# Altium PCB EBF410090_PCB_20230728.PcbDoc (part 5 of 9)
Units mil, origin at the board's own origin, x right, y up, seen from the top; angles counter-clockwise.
Board outline 5393.69 x 3858.26 mil, 6 copper layers (TOP, GND02, ART03, ART04, PWR05, BOTTOM), stack 47.2 mil thick; 570 components, 437 nets, 2015 pads, 1260 vias.
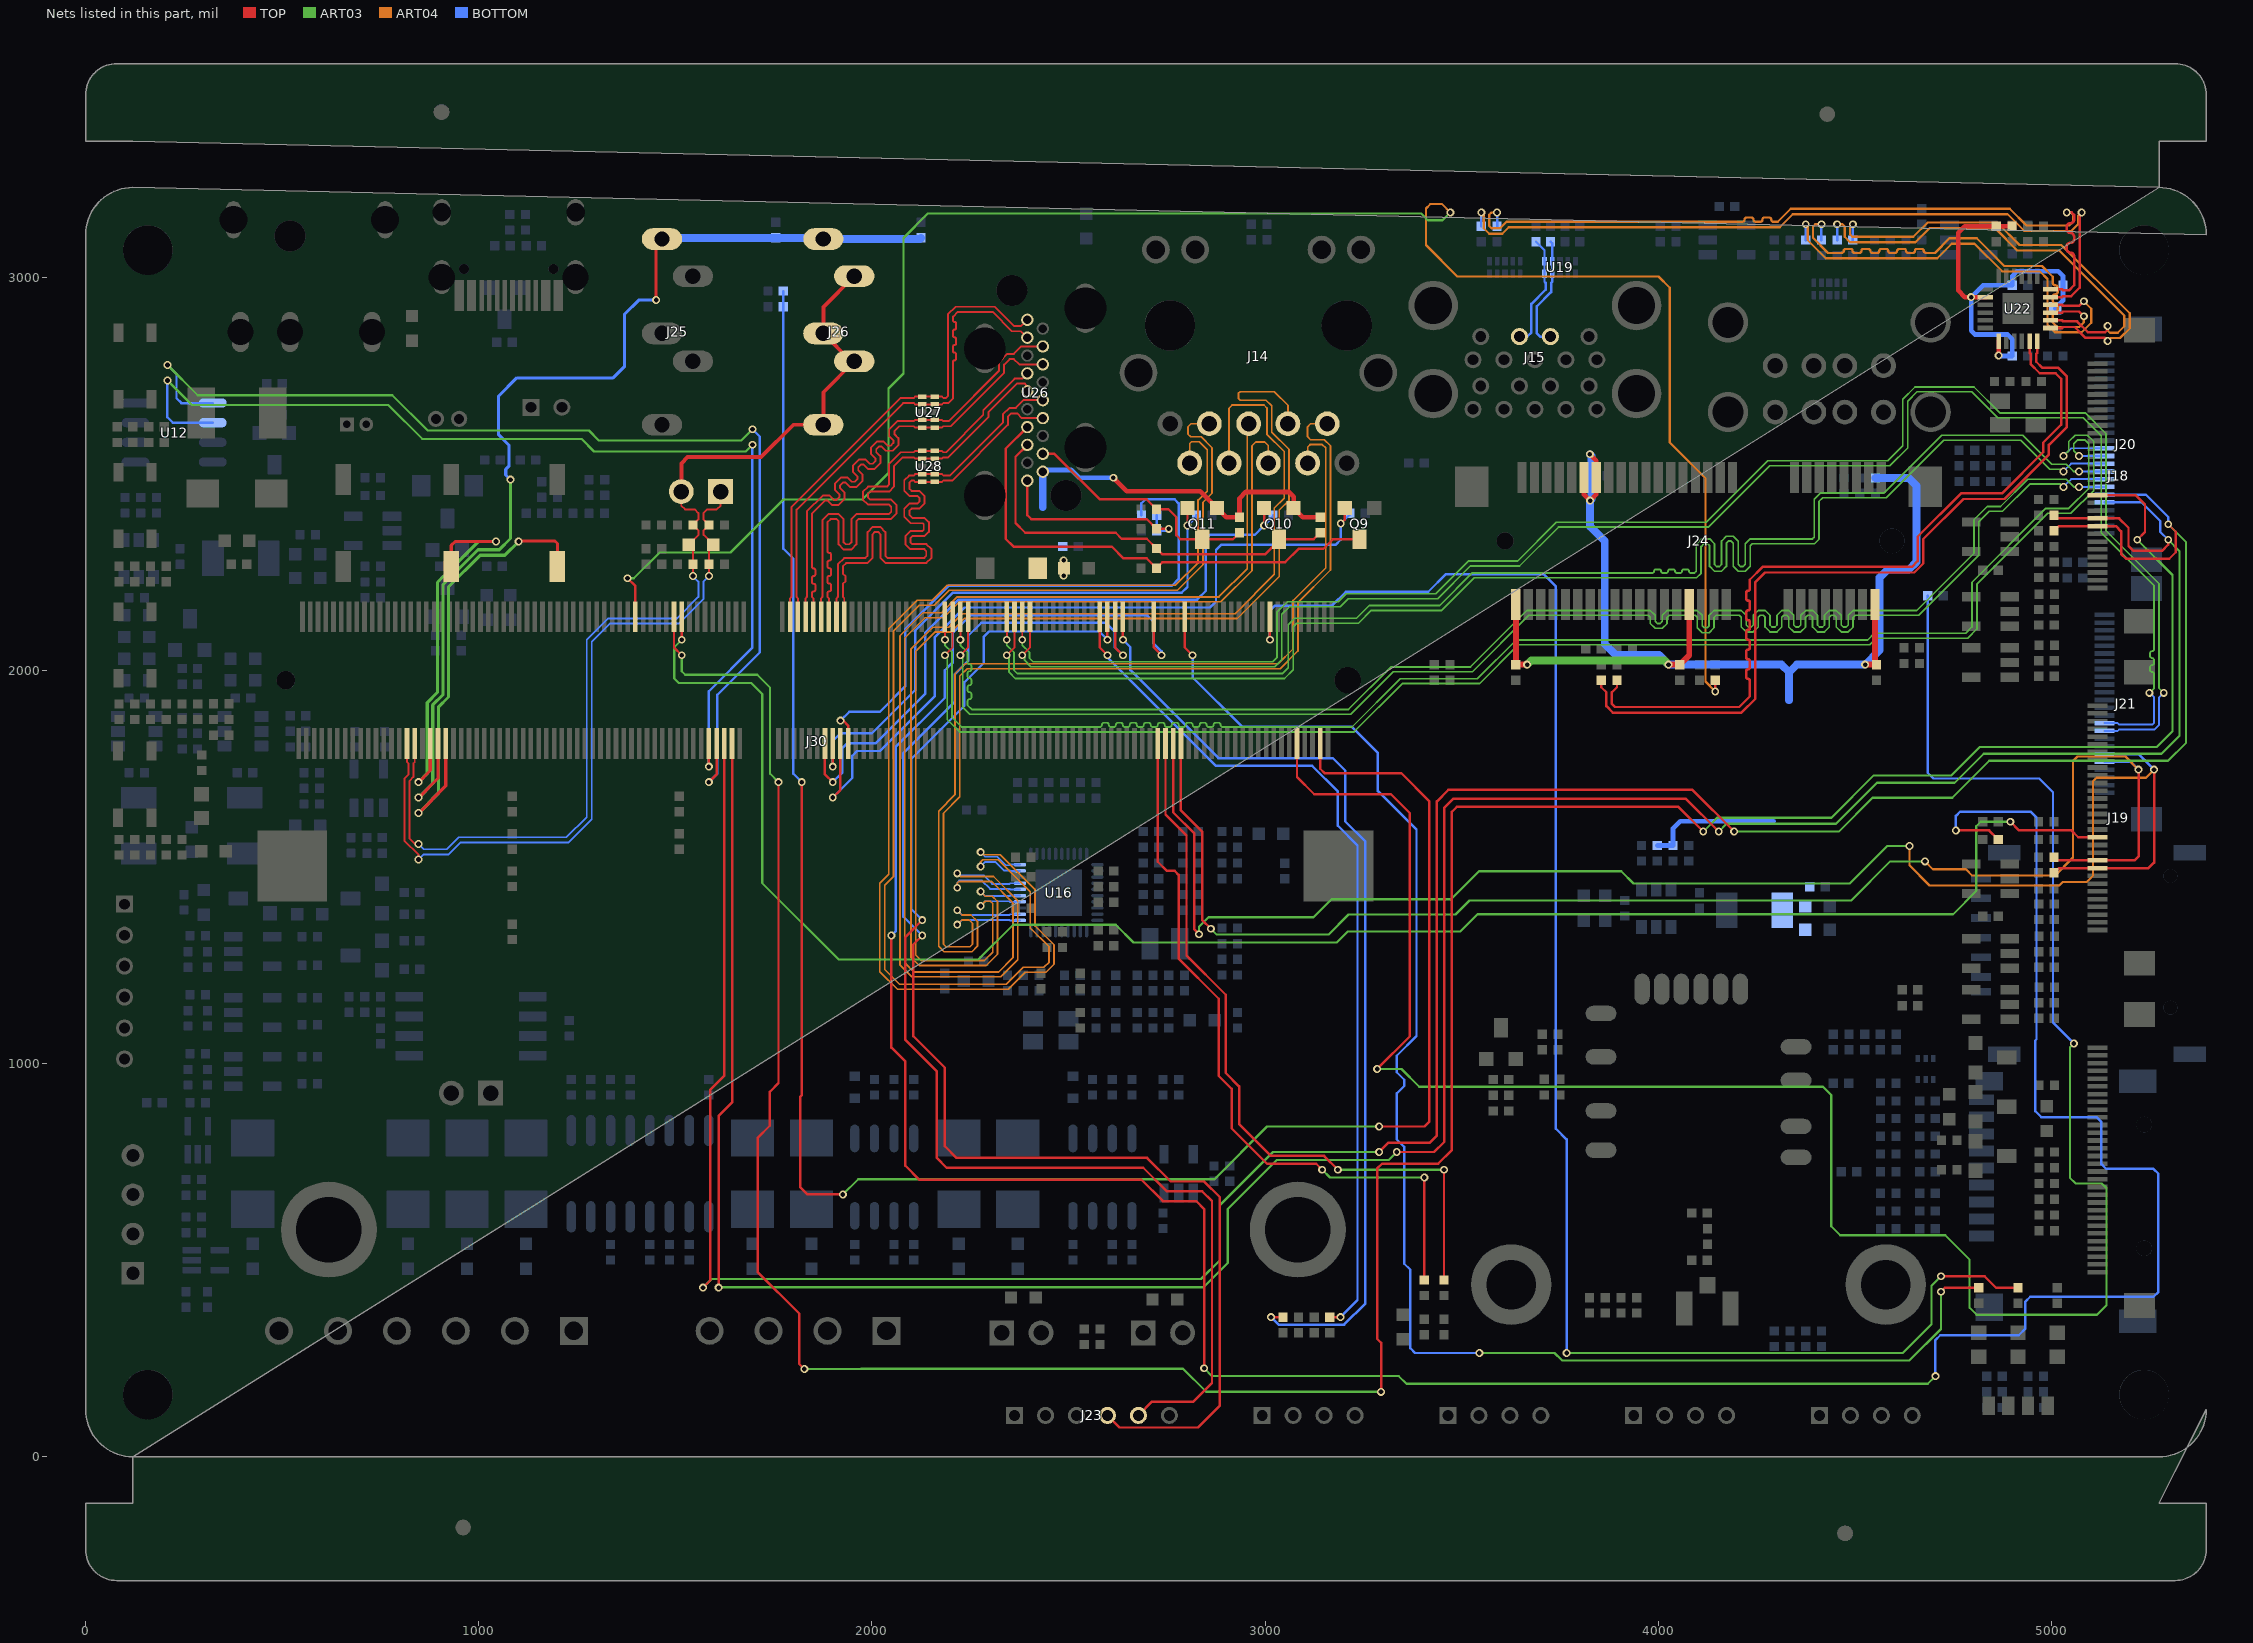
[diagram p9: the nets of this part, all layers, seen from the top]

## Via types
v1: diameter 20, hole 12, TOP to BOTTOM, 1260 vias

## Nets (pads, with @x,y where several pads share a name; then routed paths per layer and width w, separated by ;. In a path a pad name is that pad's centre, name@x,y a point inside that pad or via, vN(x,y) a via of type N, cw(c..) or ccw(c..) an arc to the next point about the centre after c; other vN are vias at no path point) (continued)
GPIO2_B7: J30.17 R48.2 | length 4171.4
  TOP w6.16: v1(3012.26,2078.07) J30.17@3012.28,2136.54 ; v1(4719,459.05) 4829.95,459.05 4859.32,429.68 R48.2@4915,429.68
  ART03 w5.61: v1(3766.91,263.81) 4622.18,263.81 4695,336.63 4695,435.05 v1(4719,459.05)
  BOTTOM w6.16: v1(3012.26,2078.07) 3012.26,2152.26 3025,2165 3170,2165 3205,2200 3415,2200 3460,2245 3708.42,2245 3739.66,2213.76 3739.66,834.34 3766.91,807.09 v1(3766.91,263.81)
GPIO2_C0: J30.39 R49.2 | length 3909.3
  TOP w6.16: J30.39@2795.74,2136.54 2795.74,2058.37 v1(2815.41,2038.7) ; v1(4719,419.68) 4729,429.68 R49.2@4815,429.68
  ART03 w5.61: v1(3545,263.81) 3736.2,263.81 3755.01,245 4639,245 4719,325 v1(4719,419.68)
  BOTTOM w6.16: v1(2815.41,2038.7) 2815.41,1982.59 2941,1857 3220,1857 3287,1790 3287,1693 3385,1595 3385,1070 3335,1020 3335,977.99 3354.08,958.91 3354.08,943.09 3335,924.01 3335,806.99 3354.08,787.91 3354.08,490.91 3369.08,475.91 3369.08,276.13 3381.4,263.81 v1(3545,263.81)
HDMI_5V: C131.1 D27.1 D32.2 Q10.1 Q11.1 R158.1 R160.1 U26.18 | length 945.4
  TOP w12: v1(2613.99,2490) 2647.99,2456 2835,2456 Q11.1@2877.5,2413.5 2901.32,2389.68 R160.1@2935,2389.68 2935,2438 2951,2454 3060.5,2454 3072.5,2442 Q10.1@3072.5,2413.5 3096.32,2389.68 R158.1@3140,2389.68
  BOTTOM w12: U26.18@2434.54,2505.36 2439.18,2510 2507,2510 2527,2490 v1(2613.99,2490)
  BOTTOM w20: 2434.54,2415.46 U26.18@2434.54,2505.36
  other v1: 2487.48,2240.63 2487.48,2280
HDMI_TX0N_PORT: J30.131 U26.9 U28.4 U28.7 | length 1279.5
  TOP w4.88: J30.131@1890.23,2136.54 1890.23,2183.41 1886.83,2186.81 1886.83,2196.69 cw(c1891.47,2196.69) 1891.47,2201.33 ; 1891.47,2220.85 cw(c1891.47,2225.49) 1886.83,2225.49 1886.83,2235.73 cw(c1891.47,2235.73) 1891.47,2240.37 ; 1891.47,2259.89 cw(c1891.47,2264.53) 1886.83,2264.53 1886.83,2274.77 cw(c1891.47,2274.77) 1891.47,2279.41 ; 1891.47,2298.93 cw(c1891.47,2303.57) 1886.83,2303.57 1886.83,2376.83 1894.61,2384.61 1910.23,2384.61 1915.11,2379.73 1915.11,2320.42 1927.53,2308 1947.97,2308 1960.39,2320.42 1960.39,2379.73 1965.27,2384.61 2047.84,2384.61 2062,2398.77 2062,2421 2047.84,2435.16 1994.76,2435.16 1989.88,2440.04 1989.88,2448.8 1995.76,2454.68 2043.58,2454.68 2056,2467.1 2056,2519.21 2078.88,2542.09 2106.53,2542.09 2109.93,2538.69 U28.7@2128.25,2538.69 U28.4@2159.75,2538.69 2178.08,2538.69 2181.48,2542.09 2193.73,2542.09 2296,2644.36 2296,2657 2368.27,2729.27 2388.73,2729.27 2395.17,2722.83 U26.9@2395.17,2709.97 ; 1891.48,2201.33 ccw(c1891.48,2205.97) 1896.12,2205.97 1896.12,2216.21 ccw(c1891.48,2216.21) 1891.48,2220.85 ; 1891.48,2240.37 ccw(c1891.48,2245.01) 1896.12,2245.01 1896.12,2255.25 ccw(c1891.48,2255.25) 1891.48,2259.89 ; 1891.48,2279.41 ccw(c1891.48,2284.05) 1896.12,2284.05 1896.12,2294.29 ccw(c1891.48,2294.29) 1891.48,2298.93
HDMI_TX0P_PORT: J30.133 U26.7 U28.5 U28.6 | length 1259
  TOP w4.88: J30.133@1870.55,2136.54 1870.55,2183.41 1873.95,2186.81 1873.95,2382.17 1889.27,2397.49 1915.57,2397.49 1927.99,2385.07 1927.99,2325.76 1932.87,2320.88 1942.63,2320.88 1947.51,2325.76 1947.51,2385.07 1959.93,2397.49 2042.5,2397.49 2049.12,2404.11 2049.12,2415.66 2042.5,2422.28 1989.42,2422.28 1977,2434.7 1977,2454.14 1990.42,2467.56 2038.24,2467.56 2043.12,2472.44 2043.12,2524.55 2073.54,2554.97 2106.53,2554.97 2109.93,2558.37 U28.6@2128.25,2558.37 U28.5@2159.75,2558.37 2178.08,2558.37 2181.48,2554.97 2188.39,2554.97 2283.12,2649.7 2283.12,2662.34 2362.93,2742.15 2381.88,2742.15 U26.7@2395.17,2755.44
HDMI_TX1N_PORT: J30.135 U26.6 U27.1 U27.10 | length 1231.2
  TOP w4.88: J30.135@1850.86,2136.54 1850.86,2183.41 1847.46,2186.81 1847.46,2196.69 cw(c1851.73,2196.69) 1851.73,2200.96 ccw(c1851.73,2205.23) 1856,2205.23 1856,2216.21 ccw(c1851.73,2216.21) 1851.73,2220.48 cw(c1851.73,2224.75) 1847.46,2224.75 1847.46,2235.73 cw(c1851.73,2235.73) 1851.73,2240 ccw(c1851.73,2244.27) 1856,2244.27 1856,2255.25 ccw(c1851.73,2255.25) 1851.73,2259.52 cw(c1851.73,2263.79) 1847.46,2263.79 1847.46,2398.91 1880.22,2431.67 1887.12,2431.67 1897.72,2421.07 1915.28,2421.07 1929.78,2435.57 1929.78,2453.13 1919.18,2463.73 1919.18,2470.63 1926.09,2477.54 1932.99,2477.54 1943.59,2466.94 1961.15,2466.94 1975.65,2481.44 1975.65,2499 1965.05,2509.6 1965.05,2516.5 1971.96,2523.41 1978.86,2523.41 1989.46,2512.81 2007.02,2512.81 2021.52,2527.31 2021.52,2544.87 2010.92,2555.47 2010.92,2562.37 2017.83,2569.28 2024.73,2569.28 2035.33,2558.68 2052.89,2558.68 2067.39,2573.18 2067.39,2590.74 2056.79,2601.34 2056.79,2608.24 2069.58,2621.03 2106.53,2621.03 2109.93,2617.63 U27.10@2128.25,2617.63 U27.1@2159.75,2617.63 2178.08,2617.63 2181.48,2621.03 2200.03,2621.03 2336,2757 2336,2778 2350,2792 2361,2792 2374.57,2778.43 U26.6@2434.54,2778.43
HDMI_TX1P_PORT: J30.137 U26.4 U27.2 U27.9 | length 1235.3
  TOP w4.88: J30.137@1831.18,2136.54 1831.18,2183.41 1834.58,2186.81 1834.58,2404.25 1874.88,2444.55 1892.46,2444.55 1903.06,2433.95 1909.94,2433.95 1916.9,2440.91 1916.9,2447.79 1906.3,2458.39 1906.3,2475.97 1920.75,2490.42 1938.33,2490.42 1948.93,2479.82 1955.81,2479.82 1962.77,2486.78 1962.77,2493.66 1952.17,2504.26 1952.17,2521.84 1966.62,2536.29 1984.2,2536.29 1994.8,2525.69 2001.68,2525.69 2008.64,2532.65 2008.64,2539.53 1998.04,2550.13 1998.04,2567.71 2012.49,2582.16 2030.07,2582.16 2040.67,2571.56 2047.55,2571.56 2054.51,2578.52 2054.51,2585.4 2043.91,2596 2043.91,2613.58 2064.24,2633.91 2106.53,2633.91 2109.93,2637.31 U27.9@2128.25,2637.31 U27.2@2159.75,2637.31 2178.08,2637.31 2181.48,2633.91 2194.69,2633.91 2323.12,2762.34 2323.12,2783.34 2344.66,2804.88 2361,2804.88 2380.06,2823.94 U26.4@2434.54,2823.94
HDMI_TX2N_PORT: J30.139 U26.3 U27.4 U27.7 | length 1248
  TOP w4.88: J30.139@1811.49,2136.54 1811.49,2183.41 1808.09,2186.81 1808.09,2409.09 2079.09,2680.09 2106.53,2680.09 2109.93,2676.69 U27.7@2128.25,2676.69 U27.4@2159.75,2676.69 2178.08,2676.69 2181.48,2680.09 2193.73,2680.09 2206.15,2692.51 2206.15,2784.83 cw(c2210.07,2784.83) 2210.07,2788.75 ; 2210.07,2808.27 cw(c2210.07,2812.19) 2206.15,2812.19 2206.15,2823.87 cw(c2210.07,2823.87) 2210.07,2827.79 ; 2210.07,2847.31 cw(c2210.07,2851.23) 2206.15,2851.23 2206.15,2862.91 cw(c2210.07,2862.91) 2210.07,2866.83 ; 2210.07,2886.35 cw(c2210.07,2890.27) 2206.15,2890.27 2206.15,2900.15 2218.12,2912.12 2306.66,2912.12 2356.11,2862.67 2378.88,2862.67 U26.3@2395.17,2846.38 ; 2210.08,2788.75 ccw(c2210.08,2792.67) 2214,2792.67 2214,2804.35 ccw(c2210.08,2804.35) 2210.08,2808.27 ; 2210.08,2827.79 ccw(c2210.08,2831.71) 2214,2831.71 2214,2843.39 ccw(c2210.08,2843.39) 2210.08,2847.31 ; 2210.08,2866.83 ccw(c2210.08,2870.75) 2214,2870.75 2214,2882.43 ccw(c2210.08,2882.43) 2210.08,2886.35
HDMI_TX2P_PORT: J30.141 U26.1 U27.5 U27.6 | length 1242.4
  TOP w4.88: J30.141@1791.81,2136.54 1791.81,2183.41 1795.21,2186.81 1795.21,2414.43 2073.75,2692.97 2106.53,2692.97 2109.93,2696.37 U27.6@2128.25,2696.37 U27.5@2159.75,2696.37 2178.08,2696.37 2181.48,2692.97 2188.39,2692.97 2193.27,2697.85 2193.27,2905.49 2212.78,2925 2312,2925 2361.45,2875.55 2378.87,2875.55 U26.1@2395.17,2891.85
HDMI_TX_CEC_PORT: D31.2 Q9.3 U26.13 | length 1268.4
  TOP w6.16: U26.13@2395.17,2619.02 2340,2563.85 2340,2335 2360,2315 2610,2315 2640,2285 2698.86,2285 D31.2@2723.86,2260 2738.86,2275 3051,2275 3085,2309 3148,2309 3172.5,2333.5 Q9.3@3240,2333.5
HDMI_TX_HPD_PORT: D28.2 R154.2 R155.1 U26.19 | length 534.4
  TOP w6.16: U26.19@2395.17,2482.61 2395.17,2394.83 2405,2385 2698.86,2385 D28.2@2723.86,2360 v1(2755,2360)
  BOTTOM w6.16: R154.2@2724.68,2395 R155.1@2724.68,2355 2750,2355 v1(2755,2360)
HDMI_TX_HPDIN: J30.126 R154.1 | length 1491.1
  TOP w6.16: v1(1919.76,1872.17) 1927.12,1872.17 1939.45,1859.84 J30.126@1939.45,1813.7
  BOTTOM w6.16: v1(1919.76,1872.17) 1942.59,1895 2020,1895 2085,1960 2085,2105 2195,2215 2762.68,2215 2780,2232.32 2780,2425 2770,2435 2695,2435 2685.32,2425.32 R154.1@2685.32,2395
HDMI_TXCLKN_PORT: J30.127 U26.12 U28.1 U28.10 | length 1303.3
  TOP w4.88: J30.127@1929.6,2136.54 1929.6,2183.41 1926.2,2186.81 1926.2,2220.07 1933,2226.87 1933,2239.59 1926.2,2246.39 1926.2,2264.98 1934.22,2273 1959.86,2273 1960.3,2273.44 1988.84,2273.44 2001.66,2286.26 2001.66,2346.4 2007.38,2352.12 2015.46,2352.12 2021.18,2346.4 2021.18,2286.26 2034,2273.44 2138.58,2273.44 2151,2285.86 2151,2309.06 2138.58,2321.48 2102.88,2321.48 2098,2326.36 2098,2336.24 2103.72,2341.96 2134.3,2341.96 2144.56,2352.22 2144.56,2376.98 2134.3,2387.24 2103.72,2387.24 2095,2395.96 2095,2405.84 2100.72,2411.56 2120.74,2411.56 2134,2424.82 2134,2443.58 2120.74,2456.84 2100.72,2456.84 2095,2462.56 2095,2477.89 2099.88,2482.77 2106.79,2482.77 2109.93,2479.63 U28.10@2128.25,2479.63 U28.1@2159.75,2479.63 2178.08,2479.63 2181.48,2483.03 2204.25,2483.03 2345.88,2624.66 2345.88,2645.65 2354.23,2654 2369,2654 2381.1,2641.9 U26.12@2434.54,2641.9
HDMI_TXCLKP_PORT: J30.129 U26.10 U28.2 U28.9 | length 1322.7
  TOP w4.88: J30.129@1909.92,2136.54 1909.92,2183.41 1913.32,2186.81 1913.32,2270.32 1928.88,2285.88 1954.52,2285.88 1954.96,2286.32 1983.5,2286.32 1988.78,2291.6 1988.78,2351.74 2002.04,2365 2020.8,2365 2034.06,2351.74 2034.06,2291.6 2039.34,2286.32 2133.24,2286.32 2138.12,2291.2 2138.12,2303.72 2133.24,2308.6 2097.54,2308.6 2085.12,2321.02 2085.12,2341.58 2098.38,2354.84 2128.96,2354.84 2131.68,2357.56 2131.68,2371.64 2128.96,2374.36 2098.38,2374.36 2082.12,2390.62 2082.12,2411.18 2095.38,2424.44 2115.4,2424.44 2121.12,2430.16 2121.12,2438.24 2115.4,2443.96 2095.38,2443.96 2082.12,2457.22 2082.12,2483.23 2094.54,2495.65 2106.27,2495.65 2109.93,2499.31 U28.9@2128.25,2499.31 U28.2@2159.75,2499.31 2178.08,2499.31 2181.48,2495.91 2198.91,2495.91 2333,2630 2333,2650.99 2350.01,2668 2366,2668 2385.41,2687.41 U26.10@2434.54,2687.41
HDMI_TXDDC_SCL_PORT: D30.2 Q10.3 R158.2 U26.15 | length 1044.1
  TOP w6.16: U26.15@2395.17,2573.54 2365,2543.37 2365,2375 2390,2350 2620,2350 2635,2335 2698.86,2335 D30.2@2723.86,2310 2738.86,2295 3000,2295 3035,2330 Q10.3@3035,2333.5 3123.18,2333.5 R158.2@3140,2350.32
HDMI_TXDDC_SDA_PORT: D29.2 Q11.3 R160.2 U26.16 | length 624.3
  TOP w6.16: U26.16@2434.54,2550.87 2464.13,2550.87 2580,2435 2698.86,2435 D29.2@2723.86,2410 2754,2410 2774.08,2389.92 2774.08,2344.08 2784.66,2333.5 Q11.3@2840,2333.5 2918.18,2333.5 R160.2@2935,2350.32
HDMITX_CEC_M0: J30.128 Q9.2 R156.2 | length 2028.2
  TOP w6.16: v1(1900.08,1676.49) 1919.76,1696.17 J30.128@1919.76,1813.7 ; v1(3192.5,2373.5) 3202.5,2383.5 Q9.2@3202.5,2413.5
  BOTTOM w6.16: v1(1900.08,1676.49) 1950,1726.41 1950,1782.68 1962.32,1795 2020,1795 2160,1935 2160,2085 2235,2160 2860,2160 2875,2175 2875,2305.84 2889.16,2320 3180.18,2320 3192.5,2332.32 v1(3192.5,2373.5) 3215.32,2396.32 R156.2@3215.32,2400
HDMITX_SCL: J30.132 Q10.2 R157.2 | length 1759
  TOP w6.16: J30.132@1880.39,1813.7 1880.39,1735.55 v1(1900.08,1715.86) ; v1(2997.5,2368.5) Q10.2@2997.5,2413.5
  BOTTOM w6.16: v1(1900.08,1715.86) 1925,1740.78 1925,1802.68 1937.32,1815 2010.01,1815 2135,1939.99 2135,2095 2220,2180 2827,2180 2849,2202 2849,2333.84 2860.16,2345 2974,2345 v1(2997.5,2368.5) 3020.32,2391.32 R157.2@3020.32,2395
HDMITX_SDA: J30.130 Q11.2 R159.2 | length 1514.1
  TOP w6.16: v1(1900.08,1755.23) J30.130@1900.08,1813.7 ; v1(2802.5,2368.5) Q11.2@2802.5,2413.5
  BOTTOM w6.16: v1(1900.08,1755.23) 1900.08,1820.07 1920.01,1840 2000,1840 2110,1950 2110,2101.71 2206.29,2198 2788,2198 2802.5,2212.5 v1(2802.5,2368.5) 2825.32,2391.32 R159.2@2825.32,2395
HOST1_DM: J15.2 R136.1 U19.4 U19.7 | length 288.5
  BOTTOM w6.23: J15.2@3725.66,2849.17 3699.65,2849.17 3691.41,2857.41 3691.41,2926.18 3727.59,2962.36 3727.59,2985.89 3730.31,2988.61 U19.4@3730.31,3009.25 U19.7@3730.31,3040.75 3730.31,3086.01 R136.1@3726,3090.32
HOST1_DP: J15.3 R137.1 U19.5 U19.6 | length 290.4
  BOTTOM w6.23: J15.3@3646.92,2849.17 3666.72,2849.17 3677.18,2859.63 3677.18,2932.08 3713.36,2968.26 3713.36,2985.89 3710.63,2988.62 U19.5@3710.63,3009.25 U19.6@3710.63,3040.75 3710.63,3068.69 R137.1@3689,3090.32
HP_DET_L: C187.1 J30.4 R218.1 | length 5175.6
  TOP w6.16: v1(1821.34,1715.86) 1821.34,919.59 1818,916.25 1818,685 1835,668 1925,668 v1(1926,667) ; J30.4@3140.24,1813.7 3140.24,1749.76 3151.16,1738.84 3346.16,1738.84 3418,1667 3418,852.32 3405.68,840 v1(3290,840)
  ART03 w5.61: v1(1926,667) 1965,706 2871,706 3005,840 v1(3290,840)
  BOTTOM w6.16: R218.1@1774.68,2965 C187.1@1774.68,2925 1774.68,2309.32 1800,2284 1800,1737.2 v1(1821.34,1715.86)
HP_SNS: J25.1 J26.1 J30.224 R219.1 R221.1 | length 2731.1
  TOP w8: v1(846.76,1676.49) 896.13,1725.86 J30.224@896.13,1813.7 ; v1(1451,2942) 1451,3082.36 J25.1@1465.96,3097.32
  ART03 w8: v1(846.76,1676.49) 883,1712.73 883,1912.2 909,1938.2 909,2218.2 997.8,2307 1052,2307 1080.63,2335.63 v1(1080.63,2485.24)
  BOTTOM w8: v1(1080.63,2485.24) 1068.68,2497.19 1068.68,2511.25 1076.48,2519.05 1076.48,2573.51 1049.72,2600.27 1049.72,2696.88 1096.84,2744 1341.6,2744 1371,2773.4 1371,2906.63 1406.37,2942 v1(1451,2942)
  BOTTOM w20: J25.1@1465.96,3097.32 1468.96,3100.32 R219.1@1755,3100.32 1873.18,3100.32 J26.1@1876.18,3097.32 2122,3097.32 R221.1@2125,3100.32
HPL_OUT: C189.1 J30.226 | length 1001.4
  TOP w8: v1(846.76,1715.86) 876.45,1745.55 J30.226@876.45,1813.7 ; C189.1@930,2264.76 930,2318 940,2328 1042,2328 1042.28,2327.72 v1(1043.82,2327.72)
  ART03 w8: v1(846.76,1715.86) 869,1738.1 869,1918 895,1944 895,2224 998.72,2327.72 v1(1043.82,2327.72)
HPR_OUT: C190.1 J30.222 | length 1198
  TOP w8: v1(846.76,1637.12) 915.82,1706.18 J30.222@915.82,1813.7 ; v1(1101.37,2328) 1102.37,2329 1193.84,2329 1200,2322.84 C190.1@1200,2264.76
  ART03 w8: v1(846.76,1637.12) 897,1687.36 897,1906.4 923,1932.4 923,2212.4 1003.6,2293 1066.37,2293 v1(1101.37,2328)
HUB_3V3: C128.1 C129.1 C130.1 R145.1 R146.1 R152.2 U22.1 U22.20 | length 1048.7
  TOP w12: U22.20@4832.32,2949.53 v1(4795.79,2949.53) 4780,2949.53 4763,2966.53 4763,3112.68 4780,3129.68 R146.1@4860,3129.68 R145.1@4900,3129.68 ; v1(4865.79,2800.79) U22.1@4865.79,2837.32
  BOTTOM w12: v1(4865.79,2800.79) 4866.58,2800 C130.1@4900.32,2800 4900.32,2842.68 4888.32,2854.68 4805,2854.68 4795.79,2863.89 v1(4795.79,2949.53) 4826.26,2980 C129.1@4900.32,2980 4900.32,3003 4912.32,3015 5017.68,3015 5029.68,3003 C128.1@5029.68,2980 5029.68,2941.18 R152.2@5010,2921.5
HUB_DM1: R130.2 U22.11 | length 1952.1
  TOP w6.23: U22.11@4997.68,2949.53 5027.18,2949.53 5029.9,2952.25 5050.44,2952.25 5072,2973.81 5072,3160.12 v1(5076.88,3165)
  ART04 w5.66: v1(3550,3165) 3556.34,3158.66 3556.34,3124.51 3570.01,3110.84 3603.15,3110.84 3619.65,3127.34 4309.34,3127.34 4342.34,3160.34 4888.66,3160.34 4931,3118 5051.06,3118 5068.47,3135.41 5068.47,3156.59 v1(5076.88,3165)
  BOTTOM w6.23: R130.2@3550,3129.68 v1(3550,3165)
HUB_DM2: R139.2 U22.9 | length 1171.2
  TOP w6.23: U22.9@4997.68,2910.16 5027.18,2910.16 5029.9,2912.88 5070.63,2912.88 v1(5082.5,2901.01)
  ART04 w5.66: v1(4415,3135) 4399.49,3135 4393.83,3129.34 4393.83,3100.17 4432,3062 4466.64,3062 ccw(c4466.64,3067) 4471.64,3067 cw(c4476.64,3067) 4476.64,3072 4489.28,3072 cw(c4489.28,3067) 4494.28,3067 ccw(c4499.28,3067) 4499.28,3062 4511.92,3062 ccw(c4511.92,3067) 4516.92,3067 cw(c4521.92,3067) 4521.92,3072 4534.56,3072 cw(c4534.56,3067) 4539.56,3067 ccw(c4544.56,3067) 4544.56,3062 4557.2,3062 ccw(c4557.2,3067) 4562.2,3067 cw(c4567.2,3067) 4567.2,3072 4579.84,3072 cw(c4579.84,3067) 4584.84,3067 ccw(c4589.84,3067) 4589.84,3062 4602.48,3062 ccw(c4602.48,3067) 4607.48,3067 cw(c4612.48,3067) 4612.48,3072 4625.12,3072 cw(c4625.12,3067) 4630.12,3067 ccw(c4635.12,3067) 4635.12,3062 4647.76,3062 ccw(c4647.76,3067) 4652.76,3067 cw(c4657.76,3067) 4657.76,3072 4670.4,3072 cw(c4670.4,3067) 4675.4,3067 ccw(c4680.4,3067) 4680.4,3062 4704,3062 4741,3099 4810,3099 4880.34,3028.66 4976.33,3028.66 5003.63,3001.36 5003.63,2985.62 ccw(c5009.81,2985.62) 5009.81,2979.44 cw(c5009.82,2973.26) 5016,2973.26 5016,2962.98 cw(c5009.82,2962.98) 5009.82,2956.8 ccw(c5009.81,2950.62) 5003.63,2950.62 5003.63,2940.34 ccw(c5009.81,2940.34) 5009.81,2934.16 cw(c5009.82,2927.98) 5016,2927.98 5016,2917.7 cw(c5009.82,2917.7) 5009.82,2911.52 ccw(c5009.81,2905.34) 5003.63,2905.34 5003.63,2885.01 5014.95,2873.69 5071.17,2873.69 5082.5,2885.02 v1(5082.5,2901.01)
  BOTTOM w6.23: R139.2@4415,3094.68 v1(4415,3135)
HUB_DM3: R132.2 U22.7 | length 1162.5
  TOP w6.23: U22.7@4997.68,2870.79 5027.18,2870.79 5029.9,2873.51 5059.49,2873.51 5087,2846 5135.15,2846 v1(5143.03,2838.12)
  ART04 w5.66: v1(4495,3135) 4487.83,3127.83 4487.83,3108.66 4493.49,3103 4648.68,3103 4684.68,3139 4862,3139 4919,3082 5025.34,3082 5199,2908.34 5199,2869.6 5174.68,2845.28 5150.19,2845.28 v1(5143.03,2838.12)
  BOTTOM w6.23: R132.2@4495,3094.68 v1(4495,3135)
HUB_DM4: R213.2 U22.5 | length 2051.7
  TOP w6.23: R213.2@3895,1975.32 3895,1957.22 3882.11,1944.33 3882.11,1915.03 3890.14,1907 4205.86,1907 4232.65,1933.79 4232.65,1974.08 ccw(c4228.39,1974.08) 4228.39,1978.34 cw(c4228.38,1982.6) 4224.12,1982.6 4224.12,1999 cw(c4228.38,1999) 4228.38,2003.26 ccw(c4228.39,2007.52) 4232.65,2007.52 4232.65,2023.92 ccw(c4228.39,2023.92) 4228.39,2028.18 cw(c4228.38,2032.44) 4224.12,2032.44 4224.12,2048.84 cw(c4228.38,2048.84) 4228.38,2053.1 ccw(c4228.39,2057.36) 4232.65,2057.36 4232.65,2073.76 ccw(c4228.39,2073.76) 4228.39,2078.02 cw(c4228.38,2082.28) 4224.12,2082.28 4224.12,2098.68 cw(c4228.38,2098.68) 4228.38,2102.94 ccw(c4228.39,2107.2) 4232.65,2107.2 4232.65,2123.6 ccw(c4228.39,2123.6) 4228.39,2127.86 cw(c4228.38,2132.12) 4224.12,2132.12 4224.12,2148.52 cw(c4228.38,2148.52) 4228.38,2152.78 ccw(c4228.39,2157.04) 4232.65,2157.04 4232.65,2173.44 ccw(c4228.39,2173.44) 4228.39,2177.7 cw(c4228.38,2181.96) 4224.12,2181.96 4224.12,2198.36 cw(c4228.38,2198.36) 4228.38,2202.62 ccw(c4228.39,2206.88) 4232.65,2206.88 4232.65,2230.65 4265.23,2263.23 4645.1,2263.23 4659.77,2277.9 4659.77,2339.89 4770.11,2450.23 4874.41,2450.23 4979.28,2555.1 4979.28,2579.4 5025.12,2625.24 5025.12,2741.5 5010.7,2755.92 4970.43,2755.92 4947.25,2779.1 4947.25,2805.1 4944.53,2807.82 U22.5@4944.53,2837.32
HUB_DP1: R131.2 U22.12 | length 1987.6
  TOP w6.23: U22.12@4997.68,2969.21 5027.17,2969.21 5029.9,2966.48 5044.54,2966.48 5057.77,2979.71 5057.77,3053.36 ccw(c5048.39,3053.36) 5048.39,3062.74 cw(c5048.38,3072.12) 5039,3072.12 5039,3078.28 cw(c5048.38,3078.28) 5048.38,3087.66 ccw(c5048.39,3097.04) 5057.77,3097.04 5057.77,3103.2 ccw(c5048.39,3103.2) 5048.39,3112.58 cw(c5048.38,3121.96) 5039,3121.96 5039,3128.12 cw(c5048.38,3128.12) 5048.38,3137.5 ccw(c5048.39,3146.88) 5057.77,3146.88 5057.77,3158.77 5051.54,3165 v1(5038.9,3165)
  ART04 w5.66: v1(3590,3165) 3575.66,3165 3570,3159.34 3570,3130.17 3575.67,3124.5 3597.49,3124.5 3613.99,3141 4214.1,3141 ccw(c4214.1,3146.5) 4219.6,3146.5 cw(c4225.1,3146.5) 4225.1,3152 4236.74,3152 cw(c4236.74,3146.5) 4242.24,3146.5 ccw(c4247.74,3146.5) 4247.74,3141 4259.38,3141 ccw(c4259.38,3146.5) 4264.88,3146.5 cw(c4270.38,3146.5) 4270.38,3152 4282.02,3152 cw(c4282.02,3146.5) 4287.52,3146.5 ccw(c4293.02,3146.5) 4293.02,3141 4303.68,3141 4336.68,3174 4894.32,3174 4936.66,3131.66 5045.4,3131.66 5054.81,3141.07 5054.81,3159.33 5049.14,3165 v1(5038.9,3165)
  BOTTOM w6.23: R131.2@3590,3129.68 v1(3590,3165)
HUB_DP2: R140.2 U22.10 | length 1163.3
  TOP w6.23: U22.10@4997.68,2929.84 5027.17,2929.84 5029.9,2927.11 5070.62,2927.11 v1(5082.5,2938.99)
  ART04 w5.66: v1(4375,3135) 4380.17,3129.83 4380.17,3094.51 4426.34,3048.34 4709.66,3048.34 4746.66,3085.34 4804.34,3085.34 4874.68,3015 4970.67,3015 4989.97,2995.7 4989.97,2879.35 5009.29,2860.03 5076.83,2860.03 5101.33,2884.53 5101.33,2920.16 v1(5082.5,2938.99)
  BOTTOM w6.23: R140.2@4375,3094.68 v1(4375,3135)
HUB_DP3: R133.2 U22.8 | length 1172.6
  TOP w6.23: U22.8@4997.68,2890.47 5027.17,2890.47 5029.9,2887.74 5065.39,2887.74 5092.9,2860.23 5136.8,2860.23 5143.03,2866.46 v1(5143.03,2876.1)
  ART04 w5.66: v1(4455,3135) 4468.51,3135 4474.17,3129.34 4474.17,3103 4487.83,3089.34 4654.34,3089.34 4690.34,3125.34 4856.34,3125.34 4913.34,3068.34 5019.68,3068.34 5185.34,2902.68 5185.34,2875.26 5169.02,2858.94 5148.69,2858.94 5143.03,2864.6 v1(5143.03,2876.1)
  BOTTOM w6.23: R133.2@4455,3094.68 v1(4455,3135)
HUB_DP4: R214.2 U22.6 | length 2050.1
  TOP w6.23: R214.2@3855,1975.32 3855,1957.21 3867.88,1944.33 3867.88,1909.13 3884.24,1892.77 4211.76,1892.77 4246.88,1927.89 4246.88,2224.75 4271.13,2249 4651,2249 4674,2272 4674,2333.99 4776.01,2436 4880.31,2436 4993.51,2549.2 4993.51,2573.5 5039.35,2619.34 5039.35,2747.4 5016.6,2770.15 4976.33,2770.15 4961.48,2785 4961.48,2805.1 4964.21,2807.83 U22.6@4964.21,2837.32
I2C0_SCL_PMIC: J30.154 U12.6 | length 2707.2
  TOP w6.16: v1(1585.11,1755.23) J30.154@1585.11,1813.7
  ART03 w5.61: v1(207.99,2737.38) 270.37,2675 769.99,2675 855.99,2589 1260.99,2589 1292.99,2557 1679.11,2557 v1(1696,2573.89)
  BOTTOM w6.16: v1(207.99,2737.38) 207.99,2644.02 221.94,2630.07 U12.6@323.28,2630.07 ; v1(1585.11,1755.23) 1585.11,1947.07 1696,2057.96 v1(1696,2573.89)
I2C0_SDA_PMIC: J30.152 U12.5 | length 2835.5
  TOP w6.16: v1(1585.11,1715.86) 1604.79,1735.54 J30.152@1604.79,1813.7
  ART03 w5.61: v1(207.99,2776.75) 284.74,2700 780,2700 870,2610 1280,2610 1305,2585 1667.74,2585 v1(1696,2613.26)
  BOTTOM w6.16: v1(207.99,2776.75) 231,2753.74 231,2692.39 243.32,2680.07 U12.5@323.28,2680.07 ; v1(1585.11,1715.86) 1607,1737.75 1607,1938 1715.08,2046.08 1715.08,2594.18 v1(1696,2613.26)
I2C1_SCL: J18.9 J20.6 J30.150 R164.2 | length 7667
  TOP w6.16: v1(1570,430) 1589,449 1589,934 1624.48,969.48 J30.150@1624.48,1813.7 ; v1(3290,775) 3314.08,799.08 3419.08,799.08 3437,817 3437,1667 3466,1696 4087.11,1696 v1(4193.11,1590) ; R164.2@5006.68,2355 5018.73,2367.05 J18.9@5117.47,2367.05 5164.1,2367.05 5177.39,2353.76 5177.39,2296.45 5189.71,2284.13 5299.68,2284.13 5316.13,2300.58 5316.13,2352.61 v1(5297.05,2371.69)
  ART03 w5.61: v1(1570,430) 1592,452 2837,452 2885,500 2885,640 3020,775 v1(3290,775) ; v1(4193.11,1590) 4459,1590 4545,1676 4748,1676 4842,1770 5296.61,1770 5342.61,1816 5342.61,2326.13 v1(5297.05,2371.69)
  BOTTOM w6.16: J20.6@5135.46,2447.05 5239.96,2447.05 5297.05,2389.96 v1(5297.05,2371.69)
I2C1_SDA: J18.10 J20.5 J30.148 R168.2 | length 7445
  TOP w6.16: v1(1610,430) 1610,867 1644.16,901.16 J30.148@1644.16,1813.7 ; v1(3335,775) 3430,775 3456,801 3456,1651 3479,1674 4069.74,1674 v1(4153.74,1590) ; R168.2@5006.68,2395 5014.94,2386.74 J18.10@5117.47,2386.74 5172.26,2386.74 5196.13,2362.87 5196.13,2316.32 5208.45,2304 5281.01,2304 5297.05,2320.04 v1(5297.05,2332.32)
  ART03 w5.61: v1(1610,430) 1611,431 2843.29,431 2905,492.71 2905,630 3030,755 3315,755 v1(3335,775) ; v1(4153.74,1590) 4173.74,1610 4452.22,1610 4556.27,1714.05 4753.85,1714.05 4827.85,1788.05 5280.05,1788.05 5326,1834 5326,2303.37 v1(5297.05,2332.32)
  BOTTOM w6.16: J20.5@5135.46,2427.36 5229.64,2427.36 5277,2380 5277,2352.37 v1(5297.05,2332.32)
I2C2_SCL_M1: J30.55 R222.2 | length 2473.1
  TOP w6.16: v1@2638.26,2078.08 J30.55@2638.26,2136.54 ; v1(3015,355) R222.2@3045.32,355
  BOTTOM w6.16: v1(2638.25,2078.07) 2657.33,2058.99 2657.33,2000.67 2881,1777 3172,1777 3204,1745 3204,1616 3255,1565 3255,390 3200.92,335.92 3034.08,335.92 v1(3015,355)
I2C2_SDA_M1: J30.61 R233.2 | length 2241.5
  TOP w6.16: J30.61@2579.21,2136.54 2579.21,2058.37 v1(2598.88,2038.7) ; R233.2@3164.68,355 v1(3191.48,355)
  BOTTOM w6.16: v1(2598.88,2038.7) 2598.88,2033.12 2875,1757 3120,1757 3185,1692 3185,1605 3235,1555 3235,398.52 v1(3191.48,355)
I2C3_SCL_M0: J30.46 R237.2 | length 1870.4
  TOP w6.16: J30.46@2726.85,1813.7 2726.85,1513.15 2750,1490 2770,1490 2780,1480 2780,1267 2882,1165 2882,968.64 2915.22,935.42 2915.22,834.78 3005,745 3130,745 v1(3145,730) ; R237.2@3405,449.68 v1(3405,710)
  ART03 w5.61: v1(3145,730) 3165,710 v1(3405,710)
I2C3_SDA_M0: J30.44 R238.2 | length 1894.7
  TOP w6.16: J30.44@2746.53,1813.7 2746.53,1633.47 2800,1580 2800,1275 2900,1175 2900,976 2934,942 2934,846 3015,765 3150,765 v1(3185,730) ; R238.2@3455,449.68 v1(3455,730)
  ART03 w5.61: v1(3185,730) v1(3455,730)
I2C4_SCL_M0: J23.4 J30.57 | length 3604.5
  TOP w6.16: v1(2128,1325.47) 2105,1302.47 2105,1070 2185,990 2185,790.01 2215.01,760 2700,760 2760,700 2845,700 2885,660 2885,130 2829.27,74.27 2629.68,74.27 J23.4@2598.94,105.01 ; J30.57@2618.58,2136.54 2618.58,2058.37 v1(2638.25,2038.7)
  BOTTOM w6.16: v1(2128,1325.47) 2080,1373.47 2080,1790.01 2210,1920.01 2210,1990 2245,2025 2245,2088 2278,2121 2595,2121 2618,2098 2618,2058.95 v1(2638.25,2038.7)
I2C4_SDA_M0: J23.5 J30.59 | length 3281.5
  TOP w6.16: v1(2128,1364.84) 2085,1321.84 2085,1060 2165,980 2165,760 2190,735 2690,735 2750,675 2840,675 2865,650 2865,187.32 2817.68,140 2712.67,140 J23.5@2677.68,105.01 ; v1(2598.88,2078.07) J30.59@2598.89,2136.54
  BOTTOM w6.16: v1(2128,1364.84) 2100,1392.84 2100,1775 2235,1910 2235,1970 2284.54,2019.54 2284.54,2085.98 2297.56,2099 2577.95,2099 v1(2598.88,2078.07)
I2C5_SCL_M0: J19.9 J21.6 J30.42 R166.2 | length 4048.2
  TOP w6.16: J30.42@2766.22,1813.7 2766.22,1638.78 2820,1585 2820,1341 v1(2832,1329) ; R166.2@5006.68,1485 5018.73,1497.05 J19.9@5117.47,1497.05 5247.05,1497.05 5261.06,1511.06 v1(5261.06,1747.68)
  ART03 w5.61: v1(2832,1329) 2832,1348.22 2855.78,1372 3123,1372 3169,1418 3473,1418 3544,1489 3906,1489 3937,1458 4487,1458 4582.63,1553.63 v1(4638.89,1553.63)
  ART04 w5.61: v1(4638.89,1553.63) 4638.89,1504.11 4690,1453 5019.91,1453 5028.72,1461.81 5089.77,1461.81 5106,1478.04 5106,1718.39 5114.61,1727 5240.38,1727 v1(5261.06,1747.68)
  BOTTOM w6.16: J21.6@5135.46,1787.05 5221.69,1787.05 v1(5261.06,1747.68)
I2C5_SDA_M0: J19.10 J21.5 J30.40 R170.2 | length 3781.5
  TOP w6.16: J30.40@2785.91,1813.7 2785.91,1644.1 2839.69,1590.32 2839.69,1365.31 v1(2862,1343) ; R170.2@5006.68,1525 5014.94,1516.74 J19.10@5117.47,1516.74 5211.74,1516.74 5221.69,1526.69 v1(5221.69,1747.68)
  ART03 w5.61: v1(2862,1343) 2877,1328 3161,1328 3212,1379 3484.01,1379 3520.01,1415 4491,1415 4590.26,1514.26 v1(4678.26,1514.26)
  ART04 w5.61: v1(4678.26,1514.26) 4698.52,1494 4783,1494 4799,1478 5009,1478 5055,1524 5055,1769.78 5066.22,1781 5188.37,1781 v1(5221.69,1747.68)
  BOTTOM w6.16: J21.5@5135.46,1767.36 5202.01,1767.36 v1(5221.69,1747.68)
LCD0_BL_PWM: J18.13 J30.163 | length 8058.4
  TOP w6.16: J30.163@1496.53,2136.54 1496.53,2058.38 v1(1516.21,2038.7) ; v1(1762.28,1715.86) 1762.28,950.28 1740,928 1740,842 1709,811 1709,470 1815,364 1815,236.04 v1(1828.02,223.02) ; v1(3295,165) 3295,289.99 3285.01,299.98 3285.01,732.68 3297.33,745 3440,745 3475,780 3475,1640.68 3487.32,1653 4051.37,1653 v1(4114.37,1590) ; J18.13@5117.47,2445.79 5214.15,2445.79 5237.99,2421.95 5237.99,2352 v1(5218.31,2332.32)
  ART03 w5.61: v1(1516.21,2038.7) 1516.21,1997.79 1525,1989 1708,1989 1741,1956 1741,1737.14 v1(1762.28,1715.86) ; v1(1828.02,223.02) 1971.42,223.02 1972.21,223.81 2791.19,223.81 2850,165 v1(3295,165) ; v1(4114.37,1590) 4149.37,1625 4440.42,1625 4548.42,1733 4746,1733 4818,1805 5268,1805 5308,1845 5308,2242.63 v1(5218.31,2332.32)
LCD1_BL_PWM: J19.13 J30.161 | length 4658.4
  TOP w6.16: v1(1516.21,2078.07) J30.161@1516.22,2136.54 ; v1(4895.63,1615) 4917.63,1593 5051,1593 5068.21,1575.79 J19.13@5117.47,1575.79
  ART03 w5.61: v1(1516.21,2078.07) 1497,2058.86 1497,1979.22 1508.22,1968 1693,1968 1721,1940 1721,1459 1915,1265 2271,1265 2359,1353 2620,1353 2665,1308 3182.01,1308 3210.01,1336 3496,1336 3540,1380 4750.01,1380 4809,1438.99 4809,1603.77 4820.23,1615 v1(4895.63,1615)
MDIN0_PHY: J14.3 U16.2 | length 2636
  ART04 w4.44: v1(2217,1389.82) 2229.04,1377.78 2252,1377.78 2268.16,1361.62 2268.16,1298.16 2254.56,1284.56 2183.16,1284.56 2169.56,1298.16 2169.56,1642.16 2211,1683.6 2211,1990.84 2237.16,2017 3033.4,2017 3071,2054.6 3071,2177.6 3154,2260.6 3154,2566 3145.58,2574.42 3114.42,2574.42 3108.13,2568.13 J14.3@3108.13,2527.52
  BOTTOM w4.88: v1(2217,1389.82) 2228.82,1378 2349.48,1378 2351.36,1379.88 U16.2@2376.57,1379.88
MDIN1_PHY: J14.7 U16.5 | length 3014.9
  ART04 w4.44: v1(2276.36,1437.51) 2288.39,1425.48 2306.12,1425.48 2319.41,1412.19 2319.41,1278.41 2290.56,1249.56 2120.44,1249.56 2099.1,1270.9 2099.1,2054.1 2155,2110 2195,2110 2229.44,2144.44 2923.84,2144.44 3023.56,2244.16 3023.56,2413.16 3048.56,2438.16 3048.56,2556.84 3004.56,2600.84 3004.56,2667.56 2997.12,2675 2916,2675 2908.13,2667.13 J14.7@2908.13,2527.52
  BOTTOM w4.88: v1(2276.36,1437.51) 2288.18,1425.69 2349.92,1425.69 2351.36,1427.13 U16.5@2376.57,1427.13
MDIN2_PHY: J14.6 U16.7 | length 2995.8
  ART04 w4.44: v1(2217,1483.82) 2225.04,1475.78 2309.22,1475.78 2371,1414 2371,1264 2327.56,1220.56 2101.44,1220.56 2071,1251 2071,2087.6 2129.84,2146.44 2176.84,2146.44 2217.4,2187 2882.4,2187 2954.28,2258.88 2954.28,2623.67 J14.6@2958.13,2627.52
  BOTTOM w4.88: v1(2217,1483.82) 2222.82,1478 2285,1478 2305.82,1457.18 2349.92,1457.18 2351.36,1458.62 U16.7@2376.57,1458.62
MDIN3_PHY: J14.9 U16.10 | length 3129.4
  ART04 w4.44: v1(2276.36,1537.82) 2283.18,1531 2326,1531 2415,1442 2415,1350 2463,1302 2463,1253 2442.56,1232.56 2390.16,1232.56 2346.6,1189 2065,1189 2020,1234 2020,1458.6 2042.56,1481.16 2042.56,2106.16 2114.84,2178.44 2153.44,2178.44 2191.44,2216.44 2771.84,2216.44 2829.56,2274.16 2829.56,2433.16 2852.56,2456.16 2852.56,2561.44 2832.14,2581.86 2812.86,2581.86 2808.13,2577.13 J14.9@2808.13,2527.52
  BOTTOM w4.88: v1(2276.36,1537.82) 2288.18,1526 2319,1526 2340.57,1504.43 2349.92,1504.43 2351.36,1505.87 U16.10@2376.57,1505.87
MDIP0_PHY: J14.2 U16.1 | length 2633.4
  ART04 w4.44: v1(2217,1353.31) 2229.03,1365.34 2246.84,1365.34 2255.72,1356.46 2255.72,1303.32 2249.4,1297 2188.32,1297 2182,1303.32 2182,1637 2223.44,1678.44 2223.44,1985.68 2242.32,2004.56 3038.56,2004.56 3083.44,2049.44 3083.44,2172.44 3166.44,2255.44 3166.44,2571.16 3150.74,2586.86 3115.44,2586.86 3108,2594.3 3108,2620.07 3115.45,2627.52 J14.2@3158.13,2627.52
  BOTTOM w4.88: v1(2217,1353.31) 2228.81,1365.12 2350.36,1365.12 2351.35,1364.13 U16.1@2376.57,1364.13
MDIP1_PHY: J14.4 U16.4 | length 3010.7
  ART04 w4.44: v1(2276.36,1401) 2288.4,1413.04 2300.96,1413.04 2306.97,1407.03 2306.97,1283.57 2285.4,1262 2125.6,1262 2111.54,1276.06 2111.54,2048.94 2160.16,2097.56 2200.16,2097.56 2234.6,2132 2929,2132 3036,2239 3036,2408 3061,2433 3061,2562 3017,2606 3017,2672.72 3002.28,2687.44 2936.44,2687.44 2932,2691.88 2932,2704.56 2936.44,2709 3023.69,2709 3058.13,2674.56 J14.4@3058.13,2627.52
  BOTTOM w4.88: v1(2276.36,1401) 2288.17,1412.81 2349.92,1412.81 2351.35,1411.38 U16.4@2376.57,1411.38
MDIP2_PHY: J14.5 U16.6 | length 2992.3
  ART04 w4.44: v1(2217,1447.31) 2217,1458.89 2221.45,1463.34 2304.06,1463.34 2358.56,1408.84 2358.56,1269.16 2322.4,1233 2106.6,1233 2083.44,1256.16 2083.44,2082.44 2135,2134 2182,2134 2222.56,2174.56 2887.56,2174.56 2966.72,2253.72 2966.72,2571.36 2976.23,2580.87 2999.25,2580.87 3008.13,2571.99 J14.5@3008.13,2527.52
  BOTTOM w4.88: v1(2217,1447.31) 2217,1460.23 2221.89,1465.12 2279.66,1465.12 2300.48,1444.3 2349.92,1444.3 2351.35,1442.87 U16.6@2376.57,1442.87
MDIP3_PHY: J14.8 U16.9 | length 3131.1
  ART04 w4.44: v1(2276.36,1501.31) 2276.36,1513.36 2281.56,1518.56 2320.84,1518.56 2402.56,1436.84 2402.56,1344.84 2450.56,1296.84 2450.56,1258.16 2437.4,1245 2385,1245 2341.44,1201.44 2070.16,1201.44 2032.44,1239.16 2032.44,1453.44 2055,1476 2055,2101 2120,2166 2158.6,2166 2196.6,2204 2777,2204 2842,2269 2842,2428 2865,2451 2865,2566.6 2837.3,2594.3 2810.7,2594.3 2804,2601 2804,2620 2811.52,2627.52 J14.8@2858.13,2627.52
  BOTTOM w4.88: v1(2276.36,1501.31) 2288.17,1513.12 2313.66,1513.12 2335.23,1491.55 2349.92,1491.55 2351.35,1490.12 U16.9@2376.57,1490.12
MIC_INN: C188.2 J27.1 J30.232 R220.1 Z10.2 | length 1916.1
  TOP w4.88: J30.232@817.39,1813.7 817.39,1766.83 820.79,1763.43 820.79,1734.65 810.89,1724.75 810.89,1567.12 846.76,1531.25 v1(846.76,1519.01) ; v1(1585.32,2240) R220.1@1585.32,2270 1585.32,2308.82 C188.2@1596.5,2320 1571.93,2344.57 1571.93,2356.61 Z10.2@1585.32,2370 1571.44,2383.88 1571.44,2399.93 1581.2,2409.69 1605.24,2409.69 1615,2419.45 J27.1@1615,2455
  BOTTOM w4.88: v1(846.76,1519.01) 860,1532.25 923.47,1532.25 953.9,1562.68 1228.33,1562.68 1287.32,1621.67 1287.32,2073.12 1333.33,2119.13 1509.13,2119.13 1571.44,2181.44 1571.44,2226.12 v1(1585.32,2240)
MIC_INP: C188.1 J26.2 J26.3 J26.4 J26.5 J27.2 J30.230 R216.2 Z7.2 | length 2810.1
  TOP w4.88: J30.230@837.08,1813.7 837.08,1766.84 833.67,1763.43 833.67,1729.31 823.77,1719.41 823.77,1572.46 837.85,1558.38 v1(846.76,1558.38) ; J27.2@1515,2455 1515,2419.45 1524.76,2409.69 1548.8,2409.69 1558.56,2399.93 1558.56,2383.88 Z7.2@1544.68,2370 1559.05,2355.63 1559.05,2345.55 C188.1@1533.5,2320 1544.68,2308.82 R216.2@1544.68,2270 v1(1544.68,2240)
  TOP w10: J27.2@1515,2455 1515,2526.84 1531.16,2543 1718,2543 1799.88,2624.88 J26.4@1876.18,2624.88 1876.18,2707.56 J26.3@1954.92,2786.3 1947.04,2786.3 J26.5@1876.18,2857.16 1876.18,2924.09 J26.2@1954.92,3002.83
  BOTTOM w4.88: v1(846.76,1558.38) 860.01,1545.13 918.13,1545.13 948.56,1575.56 1222.99,1575.56 1274.44,1627.01 1274.44,2078.46 1327.99,2132.01 1503.79,2132.01 1558.56,2186.78 1558.56,2226.12 v1(1544.68,2240)
MINIPCIE_3V3: C169.1 C173.1 C174.1 C175.1 C181.1 C182.1 C183.1 C184.1 J24.2 J24.24 J24.39 J24.41 J24.52 L10.2 R203.1 R208.1 | length 3396.8
  TOP w12: J24.41@3811.08,2490.88 3811.08,2447.51 v1(3826.83,2431.76) 3842.58,2447.51 J24.39@3842.58,2490.88 3842.58,2533.5 v1(3826.08,2550)
  TOP w15: J24.52@3637.85,2168.04 C184.1@3637.85,2014.68 v1(3666.57,2014.68) ; v1(4026.28,2014.68) C181.1@4055,2014.68 4078.8,2038.48 J24.24@4078.8,2168.04 ; v1(4526.28,2014.68) C183.1@4555,2014.68 4551.24,2018.44 J24.2@4551.24,2168.04
  ART03 w20: v1(3666.57,2014.68) 3676.89,2025 4015.96,2025 v1(4026.28,2014.68)
  BOTTOM w12: R203.1@3997.6,1554.68 C169.1@4037.6,1554.68 4037.6,1598.6 4055.6,1616.6 4293.4,1616.6
  BOTTOM w20: v1(3826.08,2550) 3830.32,2545.76 C182.1@3830.32,2495 3830.32,2435.25 v1(3826.83,2431.76) 3826.83,2366.17 3864,2329 3864,2067 3892,2039 4001.96,2039 v1(4026.28,2014.68) 4313.68,2014.68 4333,1995.36 ; 4333,1924 4333,1995.36 ; R208.1@4552.5,2489.68 4637,2489.68 4657,2469.68 4657,2276 4637,2256 4583,2256 4563,2236 4563,2051.4 v1(4526.28,2014.68) 4352.32,2014.68 4333,1995.36
MINIPCIE_NWDISABLE: J30.173 R211.2 | length 4863.6
  TOP w6.16: v1(1378.42,2234.38) 1398.11,2214.69 J30.173@1398.11,2136.54 ; v1(4145,1946.6) R211.2@4145,1975.32
  ART03 w5.61: v1(1378.42,2234.38) 1394.39,2234.38 1460.01,2300 1640,2300 1775,2435 1975,2435 2042,2502 2042,2717 2080,2755 2080,3100 2142,3162 3397,3162 3414,3145 3451.26,3145 v1(3471.26,3165)
  ART04 w5.61: v1(3471.26,3165) 3450.26,3186 3420.22,3186 3409,3174.78 3409,3082 3489,3002 4000.71,3002 4029,2973.71 4029,2579.71 4120,2488.71 4120,1971.6 v1(4145,1946.6)
MIPI0_PWR_EN: J30.10 R172.1 | length 5684.3
  TOP w6.16: J30.10@3081.18,1813.7 3081.18,1728.82 3125,1685 3320,1685 3367.84,1637.16 3367.84,1068.84 v1(3285,986)
  ART03 w5.61: v1(3285,986) 3347,986 3392,941 4419,941 4440,920 4440,585.99 4462.8,563.19 4729.81,563.19 4792,501 4792,379 4810,361 5116.01,361 5140,384.99 5140,683.39 5128.39,695 5061.61,695 5047,709.61 5047,1040.94 v1(5057.12,1051.06)
  BOTTOM w6.16: R172.1@4685.32,2190 4685.32,1739.68 4700,1725 4969,1725 5004,1690 5004,1104.18 v1(5057.12,1051.06)
MIPI1_PWR_EN: J30.47 R171.1 | length 7875.7
  TOP w6.16: v1(2049.26,1325.47) 2049.26,1040.74 2085,1005 2085,740 2120,705 2685,705 2740,650 2824.99,650 2845,629.99 v1(2845,225) ; J30.47@2717,2136.54 2717,2058.37 v1(2736.67,2038.7) ; v1(4757,1593) 4841.68,1593 R171.1@4864.68,1570
  ART03 w5.61: v1(2845,225) 2865,205 3340,205 3359.68,185.32 4685.32,185.32 v1(4705,205)
  BOTTOM w6.16: v1(2049.26,1325.47) 2060,1336.21 2060,1805 2185,1930 2185,2000 2205,2020 2205,2095 2250,2140 2700,2140 2716.38,2123.62 2716.38,2068.61 2736.67,2048.32 v1(2736.67,2038.7) ; v1(4705,205) 4705,296.68 4717.32,309 4917,309 4934,326 4934,394.68 4946.32,407 5259.68,407 5272,419.32 5272,719.68 5259.68,732 5139.32,732 5127,744.32 5127,851.56 5114.68,863.88 4974.12,863.88 4958.92,879.08 4958.92,1058.59 4962,1061.67 4962,1626 4947,1641 4768,1641 4757,1630 v1(4757,1593)
MIPI_CSI_RX_CLK0N: J20.10 J30.83 | length 3649.7
  TOP w4.88: v1(2342.99,2038.7) 2362.67,2058.38 J30.83@2362.67,2136.54
  ART03 w4.44: v1(2342.99,2038.7) 2348.77,2032.92 2348.77,1995.72 2364.93,1979.56 3049.16,1979.56 3071.44,2001.84 3071.44,2111.44 3080,2120 3237.6,2120 3270.16,2152.56 3448.91,2152.56 3531.91,2235.56 4097.29,2235.56 4109,2247.27 4109,2315 4116,2322 4125.44,2322 4130.64,2316.8 4130.64,2264.48 4143.12,2252 4160.8,2252 4173.28,2264.48 4173.28,2323.8 4178.48,2329 4185.84,2329 4191.04,2323.8 4191.04,2264.48 4203.52,2252 4221.2,2252 4233.68,2264.48 4233.68,2316.8 4238.88,2322 4397.28,2322 4409,2333.72 4409,2430 4418,2439 4579.6,2439 4726.16,2585.56 4921.84,2585.56 4995.52,2511.88 5024.85,2511.88 v1(5030.63,2506.1)
  BOTTOM w4.88: v1(5030.63,2506.1) 5050.32,2525.79 J20.10@5135.46,2525.79
MIPI_CSI_RX_CLK0P: J20.9 J30.85 | length 3653.9
  TOP w4.88: v1(2342.99,2078.07) J30.85@2342.99,2136.54
  ART03 w4.44: v1(2342.99,2078.07) 2342.99,2064.47 2361.21,2046.25 2361.21,2000.88 2370.09,1992 3044,1992 3059,2007 3059,2116.6 3074.84,2132.44 3232.44,2132.44 3265,2165 3443.75,2165 3526.75,2248 3984.89,2248 ccw(c3984.89,2252.5) 3989.39,2252.5 cw(c3993.89,2252.5) 3993.89,2257 4002.65,2257 cw(c4002.65,2252.5) 4007.15,2252.5 ccw(c4011.65,2252.5) 4011.65,2248 4020.41,2248 ccw(c4020.41,2252.5) 4024.91,2252.5 cw(c4029.41,2252.5) 4029.41,2257 4038.17,2257 cw(c4038.17,2252.5) 4042.67,2252.5 ccw(c4047.17,2252.5) 4047.17,2248 4055.93,2248 ccw(c4055.93,2252.5) 4060.43,2252.5 cw(c4064.93,2252.5) 4064.93,2257 4073.69,2257 cw(c4073.69,2252.5) 4078.19,2252.5 ccw(c4082.69,2252.5) 4082.69,2248 4092.13,2248 4096.56,2252.43 4096.56,2320.16 4110.84,2334.44 4130.6,2334.44 4143.08,2321.96 4143.08,2269.64 4148.28,2264.44 4155.64,2264.44 4160.84,2269.64 4160.84,2328.96 4173.32,2341.44 4191,2341.44 4203.48,2328.96 4203.48,2269.64 4208.68,2264.44 4216.04,2264.44 4221.24,2269.64 4221.24,2321.96 4233.72,2334.44 4392.12,2334.44 4396.56,2338.88 4396.56,2435.16 4412.84,2451.44 4574.44,2451.44 4721,2598 4927,2598 5000.68,2524.32 5038.18,2524.32 5056.4,2506.1 v1(5070,2506.1)
  BOTTOM w4.88: v1(5070,2506.1) J20.9@5135.46,2506.1
MIPI_CSI_RX_CLK1N: J21.10 J30.79 | length 4286.9
  TOP w4.88: v1(2382.36,2038.7) 2402.04,2058.38 J30.79@2402.04,2136.54
  ART03 w4.44: v1(2382.36,2038.7) 2388.14,2032.92 2388.14,2025.72 2404.3,2009.56 3024.56,2009.56 3042.44,2027.44 3042.44,2142.44 3062,2162 3191,2162 3211.56,2182.56 3439.16,2182.56 3522.16,2265.56 3647.16,2265.56 3746.16,2364.56 4127.56,2364.56 4283.56,2520.56 4589.16,2520.56 4634.44,2565.84 4634.44,2684.84 4658.16,2708.56 4797.84,2708.56 4863.84,2642.56 5080.84,2642.56 5126.56,2596.84 5126.56,2349.84 5261.22,2215.18 5261.22,2054.17 cw(c5256.11,2054.17) 5256.11,2049.06 ccw(c5256.11,2043.95) 5251,2043.95 5251,2036.41 ccw(c5256.11,2036.41) 5256.11,2031.3 cw(c5256.11,2026.19) 5261.22,2026.19 5261.22,2018.65 cw(c5256.11,2018.65) 5256.11,2013.54 ccw(c5256.11,2008.43) 5251,2008.43 5251,2000.89 ccw(c5256.11,2000.89) 5256.11,1995.78 cw(c5256.11,1990.67) 5261.22,1990.67 5261.22,1955.03 v1(5249.19,1943)
  BOTTOM w4.88: J21.10@5135.46,1865.79 5168.54,1865.79 5171.95,1862.38 5256.12,1862.38 5261,1867.26 5261,1931.19 v1(5249.19,1943)
MIPI_CSI_RX_CLK1P: J21.9 J30.81 | length 4281.9
  TOP w4.88: v1(2382.36,2078.07) J30.81@2382.36,2136.54
  ART03 w4.44: v1(2382.36,2078.07) 2382.36,2064.47 2400.58,2046.25 2400.58,2030.88 2409.46,2022 3019.4,2022 3030,2032.6 3030,2147.6 3056.84,2174.44 3185.84,2174.44 3206.4,2195 3434,2195 3517,2278 3642,2278 3741,2377 4122.4,2377 4278.4,2533 4584,2533 4622,2571 4622,2690 4653,2721 4803,2721 4869,2655 5086,2655 5139,2602 5139,2355 5273.66,2220.34 5273.66,1955.04 v1(5285.7,1943)
  BOTTOM w4.88: J21.9@5135.46,1846.1 5168.55,1846.1 5171.95,1849.5 5261.46,1849.5 5273.88,1861.92 5273.88,1931.18 v1(5285.7,1943)
MIPI_CSI_RX_D0N: J20.12 J30.99 | length 3878.6
  TOP w4.88: v1(2185.51,2038.7) 2205.19,2058.38 J30.99@2205.19,2136.54
  ART03 w4.44: v1(2185.51,2038.7) 2191.29,2032.92 2191.29,1875.11 2222.84,1843.56 2262.16,1843.56 2262.21,1843.51 3226.11,1843.51 3349.16,1966.56 3545.16,1966.56 3643.6,2065 4537.6,2065 4554.6,2082 4787,2082 4810.44,2105.44 4810.44,2218.84 4991.16,2399.56 5049.56,2399.56 5107.44,2457.44 5107.44,2582.16 5091.28,2598.32 5060.25,2598.32 5044.09,2582.16 5044.09,2558.93 v1(5030.63,2545.47)
  BOTTOM w4.88: v1(5030.63,2545.47) 5050.32,2565.16 J20.12@5135.46,2565.16
MIPI_CSI_RX_D0P: J20.11 J30.101 | length 3859.3
  TOP w4.88: v1(2185.51,2078.07) J30.101@2185.51,2136.54
  ART03 w4.44: v1(2185.51,2078.07) 2185.51,2064.47 2203.73,2046.25 2203.73,1880.27 2228,1856 2267.32,1856 2267.37,1855.95 2579.3,1855.95 ccw(c2579.3,1861.47) 2584.82,1861.47 ; 2584.82,1861.48 cw(c2590.34,1861.48) 2590.34,1867 2597.06,1867 cw(c2597.06,1861.48) 2602.58,1861.48 ; 2602.58,1861.47 ccw(c2608.1,1861.47) 2608.1,1855.95 2614.82,1855.95 ccw(c2614.82,1861.47) 2620.34,1861.47 ; 2620.34,1861.48 cw(c2625.86,1861.48) 2625.86,1867 2632.58,1867 cw(c2632.58,1861.48) 2638.1,1861.48 ; 2638.1,1861.47 ccw(c2643.62,1861.47) 2643.62,1855.95 2650.34,1855.95 ccw(c2650.34,1861.47) 2655.86,1861.47 ; 2655.86,1861.48 cw(c2661.38,1861.48) 2661.38,1867 2668.1,1867 cw(c2668.1,1861.48) 2673.62,1861.48 ; 2673.62,1861.47 ccw(c2679.14,1861.47) 2679.14,1855.95 2685.86,1855.95 ccw(c2685.86,1861.47) 2691.38,1861.47 ; 2691.38,1861.48 cw(c2696.9,1861.48) 2696.9,1867 2703.62,1867 cw(c2703.62,1861.48) 2709.14,1861.48 ; 2709.14,1861.47 ccw(c2714.66,1861.47) 2714.66,1855.95 2721.38,1855.95 ccw(c2721.38,1861.47) 2726.9,1861.47 ; 2726.9,1861.48 cw(c2732.42,1861.48) 2732.42,1867 2739.14,1867 cw(c2739.14,1861.48) 2744.66,1861.48 ; 2744.66,1861.47 ccw(c2750.18,1861.47) 2750.18,1855.95 2756.9,1855.95 ccw(c2756.9,1861.47) 2762.42,1861.47 ; 2762.42,1861.48 cw(c2767.94,1861.48) 2767.94,1867 2774.66,1867 cw(c2774.66,1861.48) 2780.18,1861.48 ; 2780.18,1861.47 ccw(c2785.7,1861.47) 2785.7,1855.95 2792.42,1855.95 ccw(c2792.42,1861.47) 2797.94,1861.47 ; 2797.94,1861.48 cw(c2803.46,1861.48) 2803.46,1867 2810.18,1867 cw(c2810.18,1861.48) 2815.7,1861.48 ; 2815.7,1861.47 ccw(c2821.22,1861.47) 2821.22,1855.95 2827.94,1855.95 ccw(c2827.94,1861.47) 2833.46,1861.47 ; 2833.46,1861.48 cw(c2838.98,1861.48) 2838.98,1867 2845.7,1867 cw(c2845.7,1861.48) 2851.22,1861.48 ; 2851.22,1861.47 ccw(c2856.74,1861.47) 2856.74,1855.95 2863.46,1855.95 ccw(c2863.46,1861.47) 2868.98,1861.47 ; 2868.98,1861.48 cw(c2874.5,1861.48) 2874.5,1867 2881.22,1867 cw(c2881.22,1861.48) 2886.74,1861.48 ; 2886.74,1861.47 ccw(c2892.26,1861.47) 2892.26,1855.95 3220.95,1855.95 3344,1979 3540,1979 3638.44,2077.44 4532.44,2077.44 4549.44,2094.44 4781.84,2094.44 4798,2110.6 4798,2224 4986,2412 5044.4,2412 5095,2462.6 5095,2577 5086.12,2585.88 5065.41,2585.88 5056.53,2577 5056.53,2558.94 v1(5070,2545.47)
  BOTTOM w4.88: v1(5070,2545.47) J20.11@5135.46,2545.47
MIPI_CSI_RX_D1N: J20.8 J30.95 | length 3885.5
  TOP w4.88: v1(2224.88,2038.7) 2244.56,2058.38 J30.95@2244.56,2136.54
  ART03 w4.44: v1(2224.88,2038.7) 2230.66,2032.92 2230.66,1906.34 2248.61,1888.39 3217.39,1888.39 3325.56,1996.56 3527.56,1996.56 3671,2140 3974.55,2140 3979.75,2134.8 3979.75,2119.48 3992.23,2107 4009.91,2107 4022.39,2119.48 4022.39,2134.8 4027.59,2140 4093.96,2140 4099.16,2134.8 4099.16,2108.48 4111.64,2096 4129.32,2096 4141.8,2108.48 4141.8,2134.8 4147,2140 4206.17,2140 4211.37,2134.8 4211.37,2110.48 4223.85,2098 4241.53,2098 4254.01,2110.48 4254.01,2134.8 4259.21,2140 4266.57,2140 4271.77,2134.8 4271.77,2110.48 4284.25,2098 4301.93,2098 4314.41,2110.48 4314.41,2134.8 4319.61,2140 4326.97,2140 4332.17,2134.8 4332.17,2110.48 4344.65,2098 4362.33,2098 4374.81,2110.48 4374.81,2134.8 4380.01,2140 4387.37,2140 4392.57,2134.8 4392.57,2110.48 4405.05,2098 4422.73,2098 4435.21,2110.48 4435.21,2134.8 4440.41,2140 4447.77,2140 4452.97,2134.8 4452.97,2110.48 4465.45,2098 4483.13,2098 4495.61,2110.48 4495.61,2134.8 4500.81,2140 4662.6,2140 4815.44,2292.84 4815.44,2377.84 4842.16,2404.56 4875.56,2404.56 4945,2474 5023.36,2474 v1(5030.63,2466.73)
  BOTTOM w4.88: v1(5030.63,2466.73) 5050.32,2486.42 J20.8@5135.46,2486.42
MIPI_CSI_RX_D1P: J20.7 J30.97 | length 3892.8
  TOP w4.88: v1(2224.88,2078.07) J30.97@2224.88,2136.54
  ART03 w4.44: v1(2224.88,2078.07) 2224.88,2064.47 2243.1,2046.25 2243.1,2020.57 ccw(c2248.05,2020.57) 2248.05,2015.62 cw(c2248.05,2010.67) 2253,2010.67 2253,2002.81 cw(c2248.05,2002.81) 2248.05,1997.86 ccw(c2248.05,1992.91) 2243.1,1992.91 2243.1,1985.05 ccw(c2248.05,1985.05) 2248.05,1980.1 cw(c2248.05,1975.15) 2253,1975.15 2253,1967.29 cw(c2248.05,1967.29) 2248.05,1962.34 ccw(c2248.05,1957.39) 2243.1,1957.39 2243.1,1949.53 ccw(c2248.05,1949.53) 2248.05,1944.58 cw(c2248.05,1939.63) 2253,1939.63 2253,1931.77 cw(c2248.05,1931.77) 2248.05,1926.82 ccw(c2248.05,1921.87) 2243.1,1921.87 2243.1,1911.5 2253.77,1900.83 3212.23,1900.83 3320.4,2009 3522.4,2009 3665.84,2152.44 3979.71,2152.44 3992.19,2139.96 3992.19,2124.64 3997.39,2119.44 4004.75,2119.44 4009.95,2124.64 4009.95,2139.96 4022.43,2152.44 4099.12,2152.44 4111.6,2139.96 4111.6,2113.64 4116.8,2108.44 4124.16,2108.44 4129.36,2113.64 4129.36,2139.96 4141.84,2152.44 4211.33,2152.44 4223.81,2139.96 4223.81,2115.64 4229.01,2110.44 4236.37,2110.44 4241.57,2115.64 4241.57,2139.96 4254.05,2152.44 4271.73,2152.44 4284.21,2139.96 4284.21,2115.64 4289.41,2110.44 4296.77,2110.44 4301.97,2115.64 4301.97,2139.96 4314.45,2152.44 4332.13,2152.44 4344.61,2139.96 4344.61,2115.64 4349.81,2110.44 4357.17,2110.44 4362.37,2115.64 4362.37,2139.96 4374.85,2152.44 4392.53,2152.44 4405.01,2139.96 4405.01,2115.64 4410.21,2110.44 4417.57,2110.44 4422.77,2115.64 4422.77,2139.96 4435.25,2152.44 4452.93,2152.44 4465.41,2139.96 4465.41,2115.64 4470.61,2110.44 4477.97,2110.44 4483.17,2115.64 4483.17,2139.96 4495.65,2152.44 4657.44,2152.44 4803,2298 4803,2383 4837,2417 4870.4,2417 4939.84,2486.44 5037.57,2486.44 5057.28,2466.73 v1(5070,2466.73)
  BOTTOM w4.88: v1(5070,2466.73) J20.7@5135.46,2466.73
